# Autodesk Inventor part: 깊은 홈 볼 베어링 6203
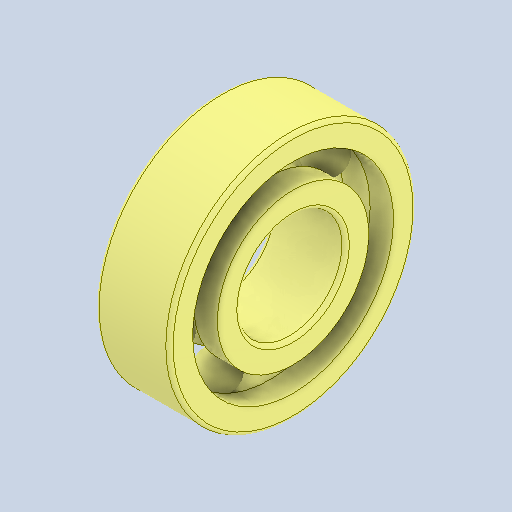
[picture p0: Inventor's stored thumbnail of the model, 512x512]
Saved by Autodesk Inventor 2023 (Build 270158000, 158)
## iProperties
Created: 2025-04
Part Number: 깊은 홈 볼 베어링 6203
Material: 강철, 연강
Description: 깊은 그루브 볼 베어링
Document SubType Name: Modeling
Designer: User
Density: 7.86 g/cm^3
Appearance: 기본값
Author: jhkim
Revision Number: 1
Sending System: Autodesk Inventor 2026
Preprocessor: ST-DEVELOPER v20.1
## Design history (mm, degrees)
feature "Solid1"
feature "Solid1:1"
feature "Solid1:2"
feature "Solid1:3"
feature "Solid1:4"
feature "Solid1:5"
feature "Solid1:6"
feature "Solid1:7"
feature "Solid1:8"
node "솔리드1"
node "솔리드2"
node "솔리드3"
node "솔리드4"
node "솔리드5"
node "솔리드6"
node "솔리드7"
node "솔리드8"
node "솔리드9"
